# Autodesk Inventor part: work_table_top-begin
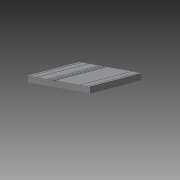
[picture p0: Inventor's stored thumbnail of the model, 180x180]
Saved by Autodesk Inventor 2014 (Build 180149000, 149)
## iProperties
Created: 2008-06
Part Number: work_table_top-begin
Document SubType Name: Modeling
Designer: Autodesk
Density: 1 g/cm^3
Material: Generic
Appearance: Default
Author: Autodesk
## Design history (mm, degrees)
sketch "Sketch1"
  geometry: L1 (-500, 0)-(500, 0); L2 (500, 0)-(500, 90); L3 (500, 90)-(-500, 90); L4 (-500, 90)-(-500, 0); 1 further point
  constraints: 8 end point, 2 parallel, 1 horizontal, 1 midpoint, 1 perpendicular
  dimensions: "d1" = 90 distance of L3.end L1.start; "d14" = 1000 distance of L2.end L3.end; "d15" = 500 distance from line of point (0, 0) L4
extrude "Extrusion1" new body sketch "Sketch1" stored distance "d2" = 1000; taper "d3" = 0 deg
sketch "Sketch2"
  geometry: L1 (-966, 73.5)-(-954, 73.5); L2 (-954, 73.5)-(-954, 67.5); L3 (-966, 67.5)-(-966, 73.5); L4 (-950.5, 67.5)-(-950.5, 60.5); L5 (-950.5, 60.5)-(-969.5, 60.5); L6 (-969.5, 60.5)-(-969.5, 67.5); L7 (-969.5, 67.5)-(-966, 67.5); L8 (-954, 67.5)-(-950.5, 67.5); L9 (-960, 46)-(-960, 11); L10 (-30, 73.5)-(30, 73.5); L11 (-1000, 73.5)-(0, 73.5) reference; 2 further points; 1 other entity
  constraints: 20 end point, 6 parallel, 4 perpendicular, 3 collinear, 3 horizontal, 1 horizontal alignment, 1 vertical alignment, 1 other
  dimensions: "d4" = 6 distance between parallel lines of L9 L3 (derived); "d6" = 9.5 distance between parallel lines of L9 L6 (derived); "d10" = 40 dimension on L9
feature "iFeature1:1" sketch "Sketch2"
pattern_linear "Rectangular Pattern1" dims "d13" = 111
mirror "Mirror1"
sketch "Sketch6"
  geometry: L1 (-185.748, 69.776)-(-34, 69.776); L2 (-34, 69.776)-(-34, 41); L3 (-34, 41)-(-185.748, 41); L4 (-185.748, 41)-(-185.748, 69.776)
  constraints: 2 other
sketch "Sketch3"
  geometry: L1 (-147.13, 73.847)-(-133.13, 73.847); L2 (-133.13, 73.847)-(-133.13, 66.847); L3 (-147.13, 66.847)-(-147.13, 73.847); L4 (-129.13, 66.847)-(-129.13, 57.847); L5 (-129.13, 57.847)-(-151.13, 57.847); L6 (-151.13, 57.847)-(-151.13, 66.847); L7 (-151.13, 66.847)-(-147.13, 66.847); L8 (-133.13, 66.847)-(-129.13, 66.847); L9 (-140.13, 45.569)-(-140.13, 9.571); L10 (-30, 73.847)-(30, 73.847); L11 (-343, 73.847)-(343, 73.847) reference
  constraints: 20 end point, 6 parallel, 4 perpendicular, 3 collinear, 3 horizontal, 1 horizontal alignment, 1 vertical alignment
  dimensions: "d20" = 7 distance between parallel lines of L9 L3 (derived); "d21" = 11 distance between parallel lines of L9 L6 (derived)
feature "iFeature1:2" sketch "Sketch3"
sketch "Sketch4"
  geometry: L1 (-109.349, 73.969)-(-91.349, 73.969); L2 (-91.349, 73.969)-(-91.349, 65.969); L3 (-109.349, 65.969)-(-109.349, 73.969); L4 (-85.849, 65.969)-(-85.849, 54.969); L5 (-85.849, 54.969)-(-114.849, 54.969); L6 (-114.849, 54.969)-(-114.849, 65.969); L7 (-114.849, 65.969)-(-109.349, 65.969); L8 (-91.349, 65.969)-(-85.849, 65.969); L9 (-100.349, 51.303)-(-100.349, 12.383); L10 (-115.831, 73.969)-(-29.907, 73.969); L11 (-133.487, 73.969)-(342.643, 73.969) reference
  constraints: 20 end point, 6 parallel, 4 perpendicular, 3 collinear, 3 horizontal, 1 horizontal alignment, 1 vertical alignment
  dimensions: "d26" = 9 distance between parallel lines of L9 L3 (derived); "d27" = 14.5 distance between parallel lines of L9 L6 (derived)
feature "iFeature1:3" sketch "Sketch4"
sketch "Sketch5"
  geometry: L1 (-71.653, 74.152)-(-49.653, 74.152); L2 (-49.653, 74.152)-(-49.653, 63.152); L3 (-71.653, 63.152)-(-71.653, 74.152); L4 (-43.153, 63.152)-(-43.153, 49.152); L5 (-43.153, 49.152)-(-78.153, 49.152); L6 (-78.153, 49.152)-(-78.153, 63.152); L7 (-78.153, 63.152)-(-71.653, 63.152); L8 (-49.653, 63.152)-(-43.153, 63.152); L9 (-60.653, 48.39)-(-60.653, 12.007); L10 (-82.653, 74.152)-(-22.653, 74.152); L11 (-91.689, 74.152)-(342.303, 74.152) reference
  constraints: 20 end point, 6 parallel, 4 perpendicular, 3 collinear, 3 horizontal, 1 horizontal alignment, 1 vertical alignment
  dimensions: "d32" = 11 distance between parallel lines of L9 L3 (derived); "d33" = 17.5 distance between parallel lines of L9 L6 (derived)
feature "iFeature1:4" sketch "Sketch5"
sketch "Sketch7"
  geometry: L1 (-187.289, 74.417)-(-175.289, 74.417); L2 (-175.289, 74.417)-(-175.289, 68.417); L3 (-187.289, 68.417)-(-187.289, 74.417); L4 (-171.789, 68.417)-(-171.789, 61.417); L5 (-171.789, 61.417)-(-190.789, 61.417); L6 (-190.789, 61.417)-(-190.789, 68.417); L7 (-190.789, 68.417)-(-187.289, 68.417); L8 (-175.289, 68.417)-(-171.789, 68.417); L9 (-181.289, 65.01)-(-181.289, 30.01); L10 (-30, 74.417)-(30, 74.417); L11 (-344.501, 74.417)-(-148.632, 74.417) reference
  constraints: 20 end point, 6 parallel, 4 perpendicular, 3 collinear, 3 horizontal, 1 horizontal alignment, 1 vertical alignment
  dimensions: "d38" = 6 distance between parallel lines of L9 L3 (derived); "d39" = 9.5 distance between parallel lines of L9 L6 (derived)
feature "iFeature1:5" sketch "Sketch7"
emboss "Emboss1" sketch "Sketch6" dims "d40" = 0.5, "d41" = 0
body "Solid1"
